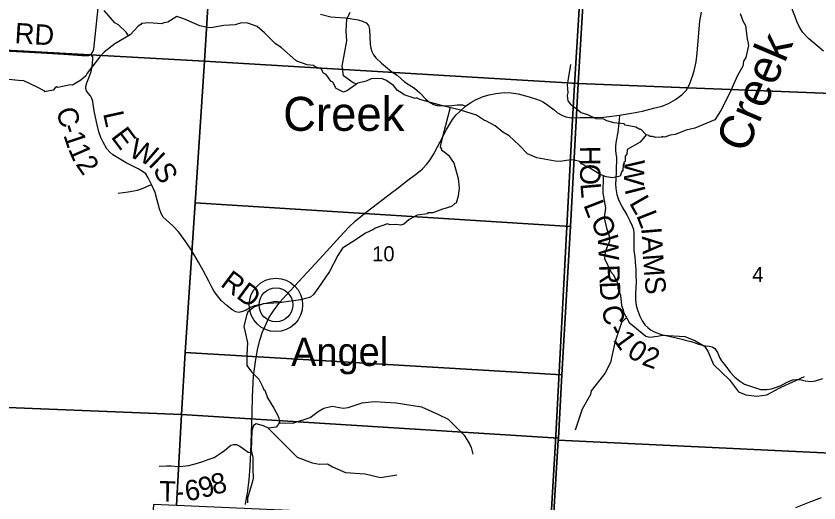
# Model space of a CAD drawing. Extents: x 1878108 to 2183446, y 146837 to 508383.
# Drawn here: x 2030457 to 2042273, y 259709 to 266876 of the extents above; entities that cross this region are included whole.
import ezdxf

# ---------------------------------------------------------------- set-up
doc = ezdxf.new("R2010")
doc.units = 0
for name, color, linetype in [('GM_X_County_Road', 7, 'Continuous'), ('GM_X_County_Road_Text', 7, 'Continuous'), ('GM_X_Minor_River', 7, 'Continuous'), ('GM_X_Minor_River_Text', 7, 'Continuous'), ('GM_X_Section', 7, 'Continuous'), ('GM_X_Section_Text', 7, 'Continuous'), ('GM_X_State_Route', 7, 'Continuous'), ('GM_X_Township', 7, 'Continuous'), ('GM_X_Township_Road', 7, 'Continuous'), ('GM_X_Township_Road_Text', 7, 'Continuous'), ('GM_X_Unincorporated', 7, 'Continuous'), ('GM_X_Unincorporated_Location', 7, 'Continuous'), ('GM_X_Unincorporated_Text', 7, 'Continuous')]:
    doc.layers.add(name, color=color, linetype=linetype)

msp = doc.modelspace()

# ---------------------------------------------------------------- linework, layer by layer
at = {"layer": 'GM_X_County_Road'}
for points in [[(2029758, 266380), (2029784, 266389), (2029844, 266386), (2030371, 266357), (2030824, 266334), (2031160, 266315), (2031425, 266297), (2031526, 266297), (2031558, 266312), (2031582, 266337), (2031600, 266390), (2031685, 267187), (2031701, 267227)], [(2042341, 266358), (2042121, 266546), (2042034, 266635), (2041985, 266713), (2041948, 266796), (2041919, 266881), (2041889, 266952), (2041868, 267010), (2041877, 267037)], [(2034938, 266903), (2035089, 266866), (2035155, 266858), (2035304, 266849), (2035492, 266820), (2035556, 266802), (2035611, 266774), (2035642, 266737), (2035656, 266679), (2035669, 266458), (2035680, 266401), (2035691, 266352), (2035716, 266304), (2035753, 266259), (2035835, 266181), (2035895, 266135), (2035987, 266055), (2036065, 266004), (2036124, 265949), (2036175, 265905), (2036243, 265863), (2036318, 265815), (2036401, 265744), (2036487, 265653), (2036546, 265602), (2036600, 265574), (2036652, 265559), (2036747, 265554), (2036872, 265559), (2036954, 265569), (2037026, 265568), (2037070, 265548)], [(2034338, 262663), (2034277, 262674), (2034083, 262636), (2033968, 262610), (2033915, 262590), (2033841, 262546), (2033776, 262521), (2033735, 262513), (2033692, 262524), (2033636, 262549), (2033558, 262615), (2033476, 262690), (2033373, 262819), (2033343, 262875), (2033294, 262974), (2033211, 263128), (2033143, 263251), (2033037, 263428), (2032956, 263554), (2032852, 263695), (2032764, 263790), (2032667, 263875), (2032622, 263917), (2032594, 263967), (2032569, 264038), (2032535, 264164), (2032503, 264279), (2032449, 264394), (2032403, 264496), (2032364, 264553), (2032319, 264588), (2032255, 264626), (2032075, 264717), (2031954, 264787), (2031879, 264832), (2031837, 264870), (2031793, 264921), (2031740, 265020), (2031704, 265090), (2031675, 265171), (2031648, 265276), (2031626, 265385), (2031605, 265482), (2031587, 265617), (2031573, 265662), (2031554, 265703), (2031517, 265741), (2031492, 265777), (2031482, 265807), (2031484, 265839), (2031497, 265892), (2031536, 265989), (2031562, 266059), (2031577, 266133), (2031585, 266242), (2031585, 266275), (2031558, 266312)], [(2039337, 265419), (2039333, 265348), (2039315, 265165), (2039290, 265040), (2039278, 264963), (2039278, 264901), (2039285, 264847), (2039292, 264798), (2039290, 264585), (2039285, 264474), (2039279, 264399), (2039285, 264336), (2039298, 264249), (2039323, 264173), (2039378, 264061), (2039443, 263951), (2039489, 263862), (2039523, 263787), (2039544, 263733), (2039550, 263675), (2039550, 263585), (2039548, 263498), (2039549, 263427), (2039550, 263419)], [(2039550, 263419), (2039561, 263338), (2039567, 263250), (2039576, 263150), (2039580, 263060), (2039581, 262961), (2039579, 262878), (2039574, 262789), (2039574, 262714), (2039580, 262650), (2039590, 262593), (2039607, 262535), (2039636, 262459), (2039671, 262390), (2039710, 262329), (2039752, 262289), (2039796, 262259), (2039874, 262218), (2039956, 262188), (2040061, 262162), (2040151, 262145), (2040257, 262120), (2040324, 262101), (2040390, 262083), (2040434, 262070), (2040500, 262045), (2040561, 262029), (2040603, 262020), (2040658, 262017), (2040703, 262005), (2040739, 261980), (2040761, 261954), (2040784, 261911), (2040811, 261850), (2040838, 261802), (2040900, 261722), (2040968, 261634), (2041037, 261558), (2041101, 261504), (2041177, 261458), (2041337, 261401), (2041413, 261379), (2041508, 261378), (2041574, 261388), (2041633, 261407), (2041701, 261434), (2041823, 261495), (2041890, 261520), (2041944, 261528), (2041992, 261525), (2042072, 261507), (2042152, 261497), (2042220, 261504), (2042331, 261539)], [(2041933, 259644), (2042130, 259721), (2042308, 259790)]]:
    msp.add_lwpolyline(points, dxfattribs=at)
at = {"layer": 'GM_X_Minor_River'}
for points in [[(2032111, 266584), (2032075, 266636), (2031966, 266744), (2031911, 266778), (2031755, 266959)], [(2035474, 265875), (2035419, 265894), (2035276, 265995), (2035257, 266140), (2035324, 266513), (2035316, 266655), (2035326, 266831), (2035375, 266932)], [(2037984, 264848), (2037860, 264974), (2037716, 265112), (2037620, 265164), (2037510, 265258), (2037371, 265334), (2037349, 265338), (2037231, 265416), (2036997, 265492), (2036720, 265559), (2036398, 265645), (2036348, 265671), (2036330, 265663), (2036167, 265714), (2036127, 265747), (2036071, 265778), (2036011, 265851), (2035897, 265931), (2035831, 265955), (2035681, 265952), (2035608, 265918), (2035588, 265912), (2035488, 265888), (2035332, 265781), (2035276, 265755), (2035169, 265811), (2035117, 265901), (2035089, 265919), (2035021, 266017), (2034981, 266035), (2034947, 266101), (2034859, 266127), (2034835, 266149), (2034741, 266159), (2034587, 266211), (2034575, 266219), (2034364, 266407), (2034270, 266473), (2034114, 266629), (2034004, 266721), (2033870, 266769), (2033776, 266775), (2033679, 266748), (2033513, 266736), (2033323, 266701), (2033272, 266709), (2033162, 266731), (2032926, 266837), (2032822, 266867), (2032691, 266784), (2032633, 266774), (2032603, 266760), (2032409, 266777), (2032305, 266765), (2032293, 266751), (2032252, 266725), (2032136, 266597)], [(2041114, 266912), (2041152, 266806), (2041192, 266736), (2041216, 266535), (2041220, 266521), (2041238, 266441), (2041196, 266266), (2041164, 266212), (2041152, 266139), (2041073, 265999), (2040957, 265738), (2040831, 265484), (2040740, 265350), (2040682, 265324), (2040445, 265227), (2040319, 265198), (2040155, 265132), (2040085, 265123), (2040006, 265091), (2039962, 265103), (2039968, 265093), (2039964, 265103), (2039968, 265093), (2039870, 265089), (2039824, 265105), (2039778, 265103), (2039776, 265117), (2039732, 265129), (2039650, 265213), (2039636, 265207), (2039578, 265239), (2039419, 265270), (2039405, 265288), (2039253, 265302), (2039171, 265326), (2039151, 265334), (2039107, 265356), (2038993, 265364), (2038873, 265420), (2038774, 265452), (2038630, 265562), (2038582, 265626), (2038570, 265708), (2038584, 265744), (2038570, 265863), (2038588, 265953), (2038621, 266164)], [(2032136, 266597), (2031908, 266467), (2031753, 266344), (2031691, 266274), (2031502, 266037), (2031482, 265995), (2031412, 265930), (2031288, 265860), (2031256, 265862), (2031073, 265825), (2031053, 265833), (2031031, 265817), (2031005, 265785), (2030877, 265762), (2030881, 265772), (2030765, 265830), (2030570, 265924), (2030494, 265926)], [(2030494, 265926), (2030350, 265942)], [(2036843, 265529), (2036707, 265001)], [(2039732, 265129), (2039642, 265018), (2039449, 264911), (2039447, 264845), (2039423, 264811), (2039419, 264735), (2039403, 264727), (2039405, 264692), (2039393, 264694), (2039387, 264590), (2039373, 264592), (2039349, 264520), (2039238, 264493), (2039140, 264507), (2039052, 264543), (2038902, 264637), (2038890, 264639), (2038780, 264701), (2038754, 264735), (2038692, 264751), (2038623, 264759), (2038463, 264734), (2038393, 264740), (2038120, 264788), (2037984, 264848)], [(2036707, 265001), (2036698, 264945), (2036716, 264921), (2036712, 264909), (2036822, 264829), (2036882, 264739), (2036900, 264717), (2036962, 264482), (2036976, 264348), (2036964, 264225), (2036935, 264119), (2036913, 264117), (2036867, 264074), (2036753, 264036), (2036733, 264032), (2036591, 263977), (2036516, 263979), (2036514, 263965), (2036362, 263943), (2036242, 263882), (2036162, 263814), (2036121, 263798), (2036055, 263808), (2035955, 263803), (2035923, 263815), (2035741, 263753), (2035715, 263735), (2035600, 263682), (2035432, 263567), (2035261, 263459), (2035193, 263350), (2035067, 263113), (2034898, 262866), (2034836, 262775), (2034792, 262739), (2034641, 262699), (2034329, 262656), (2034094, 262641), (2034060, 262627), (2033968, 262595), (2033870, 262522), (2033850, 262466), (2033842, 262450), (2033809, 262307), (2033829, 262221), (2033863, 262063), (2033855, 261892), (2033853, 261733), (2033923, 261641), (2034029, 261533), (2034089, 261413), (2034097, 261381), (2034119, 261369), (2034155, 261256), (2034249, 261102), (2034321, 260978), (2034333, 260896), (2034319, 260874), (2034313, 260861), (2034285, 260825), (2034171, 260807), (2034097, 260845), (2033992, 260871), (2033950, 260847), (2033924, 260768), (2033916, 260485), (2033940, 260377), (2033940, 260204), (2033948, 260074), (2033933, 260010), (2033863, 259779), (2033865, 259708)], [(2039097, 264525), (2039090, 264267), (2039129, 264055), (2039111, 263903), (2039146, 263752), (2039187, 263638), (2039188, 263564), (2039126, 263406), (2039117, 263308), (2039212, 263110), (2039249, 263067), (2039311, 262933), (2039311, 262868), (2039350, 262767), (2039365, 262614), (2039391, 262549), (2039396, 262517), (2039481, 262364), (2039727, 262163), (2039786, 262150), (2039896, 262164), (2039969, 262178), (2040297, 262157), (2040455, 262094), (2040586, 262016), (2040636, 261942), (2040722, 261745), (2040957, 261523), (2041087, 261346), (2041199, 261302), (2041360, 261279), (2041505, 261299), (2041687, 261397), (2041716, 261414), (2042058, 261572)], [(2039433, 262429), (2039368, 262365), (2039271, 262072), (2039206, 261775), (2039121, 261613), (2038922, 261361), (2038910, 261305), (2038790, 261091), (2038685, 260779)], [(2034327, 260890), (2034532, 260883), (2034784, 260965), (2034905, 261056), (2034986, 261103), (2035107, 261131), (2035270, 261106), (2035344, 261114), (2035549, 261183), (2035728, 261204), (2036052, 261183), (2036422, 261124), (2036674, 261009), (2036815, 260941), (2037052, 260706), (2037135, 260567), (2037156, 260527), (2037177, 260428)], [(2034165, 260810), (2034595, 260382), (2034812, 260297), (2034923, 260278), (2035039, 260282), (2035114, 260242), (2035307, 260159), (2035596, 260136), (2035818, 260081), (2036062, 260121)]]:
    msp.add_lwpolyline(points, dxfattribs=at)
at = {"layer": 'GM_X_Section'}
for points in [[(2028030, 271771), (2033552, 271475), (2033229, 266210), (2027727, 266517)], [(2033552, 271475), (2039048, 271196), (2038727, 265884), (2033229, 266210)], [(2039048, 271196), (2044660, 270918), (2044579, 269660), (2044498, 268336), (2044411, 266966), (2044328, 265661), (2038727, 265884)], [(2027727, 266517), (2033229, 266210), (2033091, 264128), (2032945, 261923), (2032890, 261012), (2029722, 261139), (2027410, 261234), (2027470, 262145), (2027599, 264349)], [(2033229, 266210), (2038727, 265884), (2038616, 263777), (2033091, 264128)], [(2044328, 265661), (2044252, 264370), (2044165, 263012), (2044077, 261679), (2043994, 260367), (2038436, 260632), (2038438, 260664), (2038491, 261596), (2038616, 263777), (2038727, 265884)], [(2038616, 263777), (2038491, 261596), (2032945, 261923), (2033091, 264128)], [(2032945, 261923), (2038491, 261596), (2038438, 260664), (2032890, 261012)], [(2032890, 261012), (2032820, 259673), (2032478, 259688), (2032295, 256825), (2029458, 256958), (2029722, 261139)], [(2038438, 260664), (2038436, 260632), (2038361, 259408), (2035474, 259551), (2032820, 259673), (2032890, 261012)], [(2043994, 260367), (2043904, 259015), (2043814, 257714), (2043726, 256349), (2043642, 255058), (2043641, 255042), (2038107, 255296), (2038361, 259408), (2038436, 260632)]]:
    msp.add_lwpolyline(points, close=True, dxfattribs=at)
at = {"layer": 'GM_X_State_Route'}
for points in [[(2036035, 264314), (2036205, 264443), (2036353, 264557), (2036433, 264623), (2036495, 264690), (2036549, 264759), (2036603, 264849), (2036659, 264952), (2036736, 265099), (2036790, 265206), (2036882, 265351), (2036935, 265422), (2036987, 265471), (2037070, 265548), (2037151, 265602), (2037226, 265646), (2037332, 265692), (2037418, 265718), (2037519, 265738), (2037643, 265748), (2037741, 265744), (2037847, 265729), (2038009, 265687), (2038133, 265646), (2038204, 265616), (2038285, 265565), (2038374, 265496), (2038426, 265453), (2038487, 265416), (2038549, 265391), (2038633, 265379), (2038648, 265379), (2038752, 265381), (2038979, 265382), (2039109, 265389), (2039184, 265399), (2039337, 265419), (2039515, 265446), (2039674, 265476), (2039837, 265518), (2039965, 265551), (2040057, 265589), (2040162, 265648), (2040259, 265719), (2040317, 265782), (2040361, 265859), (2040408, 265977), (2040437, 266069), (2040464, 266203), (2040481, 266331), (2040496, 266511), (2040520, 266802), (2040542, 266931)], [(2034338, 262663), (2034382, 262711), (2034491, 262831), (2034682, 263036), (2034977, 263358), (2035228, 263631), (2035349, 263761), (2035450, 263862), (2035608, 263990), (2036007, 264293), (2036035, 264314)], [(2033850, 259777), (2033862, 259853), (2033889, 260049), (2033903, 260244), (2033912, 260450), (2033920, 260733), (2033932, 261042), (2033938, 261270), (2033953, 261579), (2033967, 261682), (2033983, 261818), (2034011, 261963), (2034042, 262106), (2034083, 262227), (2034121, 262312), (2034179, 262431), (2034245, 262536), (2034338, 262663)], [(2033835, 259684), (2033850, 259777)]]:
    msp.add_lwpolyline(points, dxfattribs=at)
at = {"layer": 'GM_X_Township'}
for points in [[(2037354, 244623), (2037712, 249015), (2037719, 249130), (2037726, 249394), (2037730, 249514), (2037744, 249651), (2037765, 249889), (2038076, 255255), (2038232, 257876), (2038395, 260608), (2038647, 265352), (2038674, 265862), (2039007, 271286), (2039153, 273059), (2039409, 276171), (2039444, 276594), (2042678, 276439)], [(2039007, 271286), (2038674, 265862), (2038647, 265352), (2038395, 260608), (2038232, 257876), (2038076, 255255), (2037765, 249889), (2037744, 249651), (2037730, 249514), (2037726, 249394), (2037719, 249130), (2037712, 249015), (2037354, 244623)]]:
    msp.add_lwpolyline(points, dxfattribs=at)
at = {"layer": 'GM_X_Township_Road'}
for points in [[(2031958, 264270), (2032104, 264290), (2032190, 264302), (2032244, 264313), (2032303, 264332), (2032449, 264394)], [(2032564, 260250), (2032669, 260253), (2032738, 260255), (2032840, 260247), (2032909, 260250), (2032999, 260262), (2033129, 260296), (2033206, 260320), (2033285, 260349), (2033370, 260379), (2033473, 260446), (2033523, 260483), (2033617, 260558), (2033655, 260571), (2033700, 260567), (2033750, 260544), (2033820, 260494), (2033873, 260456), (2033912, 260450)]]:
    msp.add_lwpolyline(points, dxfattribs=at)
at = {"layer": 'GM_X_Unincorporated'}
for radius in [393, 249]:
    msp.add_circle((2034281, 262624), radius, dxfattribs=at)
at = {"layer": 'GM_X_Unincorporated_Location'}
msp.add_line((2034281, 262624), (2034281, 262624), dxfattribs=at)

# ---------------------------------------------------------------- texts
at = {"layer": 'GM_X_County_Road_Text'}
for s, rotation, p in [('RD', 356.5467, (2030430, 266477)), ('C', 286.8772, (2031041, 265485)), ('L', 282.361, (2031736, 265443)), ('1', 288.1955, (2031151, 265124)), ('-', 287.1602, (2031113, 265247)), ('E', 306.9638, (2031843, 265097)), ('W', 334.3897, (2032098, 264820)), ('1', 293.4754, (2031219, 264920)), ('H', 270.4517, (2038754, 264963)), ('2', 305.1273, (2031325, 264693)), ('I', 315.7314, (2032390, 264684)), ('S', 298.4736, (2032464, 264617)), ('O', 270.5895, (2038756, 264699)), ('W', 268.0851, (2039411, 264766)), ('L', 275.1722, (2038760, 264408)), ('I', 284.1903, (2039409, 264327)), ('L', 299.8274, (2039473, 264125)), ('L', 291.2729, (2038802, 264096)), ('L', 291.4457, (2039580, 263941)), ('O', 298.5018, (2038900, 263849)), ('I', 274.7828, (2039656, 263755)), ('W', 272.4964, (2039017, 263651)), ('A', 273.1818, (2039666, 263634)), ('M', 273.9872, (2039681, 263366)), ('R', 272.303, (2039036, 263211)), ('RD', 323.3346, (2033450, 262911)), ('S', 275.1606, (2039705, 263034)), ('D', 272.4218, (2039045, 262965)), ('C', 282.5703, (2039069, 262584)), ('-', 296.9471, (2039150, 262266)), ('1', 305.93, (2039233, 262113)), ('0', 327.6164, (2039431, 261879)), ('2', 340.2531, (2039652, 261748))]:
    msp.add_text(s, height=300, rotation=rotation, dxfattribs=at).set_placement(p)
at = {"layer": 'GM_X_Minor_River_Text'}
for rotation, p in [(66.9988, (2041202, 264840)), (359.997, (2034388, 265186))]:
    msp.add_text('Creek', height=500, rotation=rotation, dxfattribs=at).set_placement(p)
at = {"layer": 'GM_X_Section_Text'}
for s, p in [('10', (2035698, 263266)), ('4', (2041291, 262960))]:
    msp.add_text(s, height=221, rotation=0, dxfattribs=at).set_placement(p)
at = {"layer": 'GM_X_Township_Road_Text'}
for s, rotation, p in [('9', 17.1355, (2033193, 259773)), ('8', 13.135, (2033364, 259826)), ('T', 359.1664, (2032562, 259731)), ('6', 8.491, (2032962, 259734)), ('-', 1.4176, (2032799, 259728))]:
    msp.add_text(s, height=300, rotation=rotation, dxfattribs=at).set_placement(p)
at = {"layer": 'GM_X_Unincorporated_Text'}
msp.add_text('Angel', height=417, rotation=0, dxfattribs=at).set_placement((2034506, 261725))

doc.saveas('drawing.dxf')
